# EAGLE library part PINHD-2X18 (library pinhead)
PIN HEADER
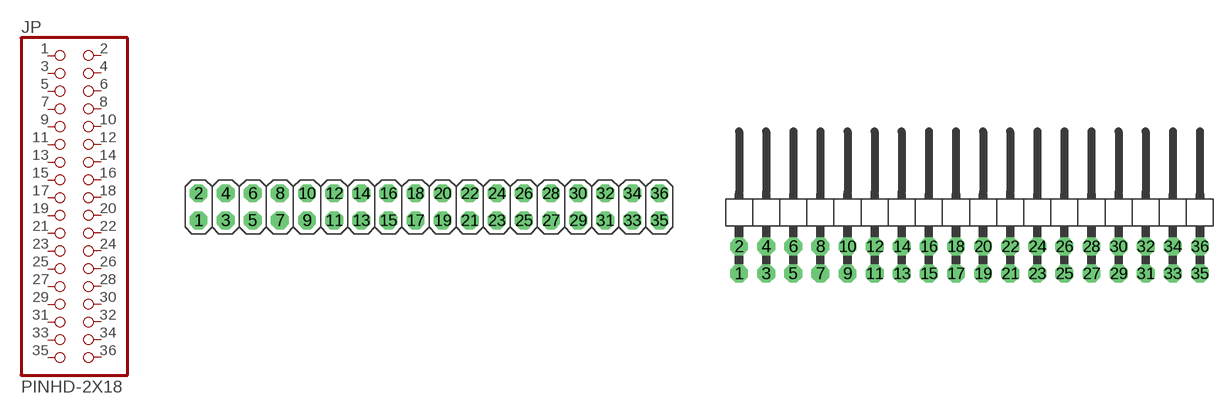
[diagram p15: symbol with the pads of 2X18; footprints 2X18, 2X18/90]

Designator prefix JP

## PINHD-2X18  [2X18]
1  1  pas
2  2  pas
3  3  pas
4  4  pas
5  5  pas
6  6  pas
7  7  pas
8  8  pas
9  9  pas
10  10  pas
11  11  pas
12  12  pas
13  13  pas
14  14  pas
15  15  pas
16  16  pas
17  17  pas
18  18  pas
19  19  pas
20  20  pas
21  21  pas
22  22  pas
23  23  pas
24  24  pas
25  25  pas
26  26  pas
27  27  pas
28  28  pas
29  29  pas
30  30  pas
31  31  pas
32  32  pas
33  33  pas
34  34  pas
35  35  pas
36  36  pas

## PINHD-2X18/90  [2X18/90]
Pads as for 2X18

## Footprint 2X18 (pad centres in mm)
PIN HEADER
drill 1.016 pad 1.67 octagon: 1 -21.59,-1.27; 2 -21.59,1.27; 3 -19.05,-1.27; 4 -19.05,1.27; 5 -16.51,-1.27; 6 -16.51,1.27; 7 -13.97,-1.27; 8 -13.97,1.27; 9 -11.43,-1.27; 10 -11.43,1.27; 11 -8.89,-1.27; 12 -8.89,1.27; 13 -6.35,-1.27; 14 -6.35,1.27; 15 -3.81,-1.27; 16 -3.81,1.27; 17 -1.27,-1.27; 18 -1.27,1.27; 19 1.27,-1.27; 20 1.27,1.27; 21 3.81,-1.27; 22 3.81,1.27; 23 6.35,-1.27; 24 6.35,1.27; 25 8.89,-1.27; 26 8.89,1.27; 27 11.43,-1.27; 28 11.43,1.27; 29 13.97,-1.27; 30 13.97,1.27; 31 16.51,-1.27; 32 16.51,1.27; 33 19.05,-1.27; 34 19.05,1.27; 35 21.59,-1.27; 36 21.59,1.27

## Footprint 2X18/90 (pad centres in mm)
PIN HEADER
drill 1.016 pad 1.67 octagon: 1 -21.59,-6.35; 2 -21.59,-3.81; 3 -19.05,-6.35; 4 -19.05,-3.81; 5 -16.51,-6.35; 6 -16.51,-3.81; 7 -13.97,-6.35; 8 -13.97,-3.81; 9 -11.43,-6.35; 10 -11.43,-3.81; 11 -8.89,-6.35; 12 -8.89,-3.81; 13 -6.35,-6.35; 14 -6.35,-3.81; 15 -3.81,-6.35; 16 -3.81,-3.81; 17 -1.27,-6.35; 18 -1.27,-3.81; 19 1.27,-6.35; 20 1.27,-3.81; 21 3.81,-6.35; 22 3.81,-3.81; 23 6.35,-6.35; 24 6.35,-3.81; 25 8.89,-6.35; 26 8.89,-3.81; 27 11.43,-6.35; 28 11.43,-3.81; 29 13.97,-6.35; 30 13.97,-3.81; 31 16.51,-6.35; 32 16.51,-3.81; 33 19.05,-6.35; 34 19.05,-3.81; 35 21.59,-6.35; 36 21.59,-3.81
